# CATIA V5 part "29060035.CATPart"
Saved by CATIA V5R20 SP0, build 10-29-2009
Part number: 29060035
Definition: NONE
Nomenclature: 29060035
Source: Unknown
Description: 29060035
Bounding box of the stored display mesh (mm): x -17.5 to 44.548, y -44 to 78.548, z -34 to 34
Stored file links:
  C:\Users\Utente\Desktop\IO LAVORO\3D X SITO CF\X SITO\PLASTICA\RF1\29060035.CATPart
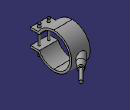
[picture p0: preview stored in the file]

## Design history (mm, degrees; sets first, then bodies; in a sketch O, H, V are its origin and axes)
Body1 "29060035" (main body)
  Solid1: solid without history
